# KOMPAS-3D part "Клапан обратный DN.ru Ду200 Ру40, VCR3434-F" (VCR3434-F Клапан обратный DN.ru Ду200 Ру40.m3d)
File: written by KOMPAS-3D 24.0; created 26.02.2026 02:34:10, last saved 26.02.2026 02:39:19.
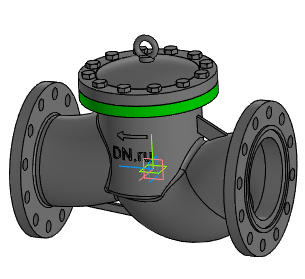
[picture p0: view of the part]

Document properties: Автор: R2D2; Полное имя файла: VCR3434-F Клапан обратный DN.ru Ду200 Ру40.cdw

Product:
- Part/product: Клапан обратный DN.ru Ду200 Ру40  | designation VCR3434-F
    Масса: 145
    Раздел спецификации: Прочие изделия
    Форматы листов документа: A2
    Примечание: D100-04061
    additional columns: D100-04061

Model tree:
1. Операция без истории:1
2. Элемент выдавливания:1  (with: Грань.Операция без истории:1)
     Расстояние 1 = 375.5
3. Скругление:1  (with: Ребро.Операция без истории:1)
     Радиус = 5

Referenced files in C:\Program Files\ASCON\KOMPAS-3D v24\Libs\EasySteel\: Rolled metal.kle, StandartSolutions.kle, DSTVProperties.lpt
Referenced files in C:\Program Files\ASCON\KOMPAS-3D v24\Templates\: Констр. чертеж А3 гориз. перв. лист.cdt
Referenced files in C:\Program Files\ASCON\KOMPAS-3D v24\Libs\EasySteel\BeltEndings\: 
Referenced files in C:\Program Files\ASCON\KOMPAS-3D v24\Libs\EasySteel\Punctures\: 
Referenced files in C:\Program Files\ASCON\KOMPAS-3D v24\Libs\EasySteel\Insulations\: 
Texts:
  Уголок равнополочный по ГОСТ 8509-93 (Спец)
  config2DpacketName
  config2DstdSizeID
  Констр. чертеж А3 гориз. перв. лист.cdt
  Болт ГОСТ 22353-77
  Шайба ГОСТ 22355-77
  Гайка ГОСТ 22354-77
  Нормальная пружинная шайба ГОСТ 6402-70 (исп. 1)
  SeaRox SL 436
  Точка начала. Х
  Точка начала. Y
  Точка начала. Z
  VCR3434-F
